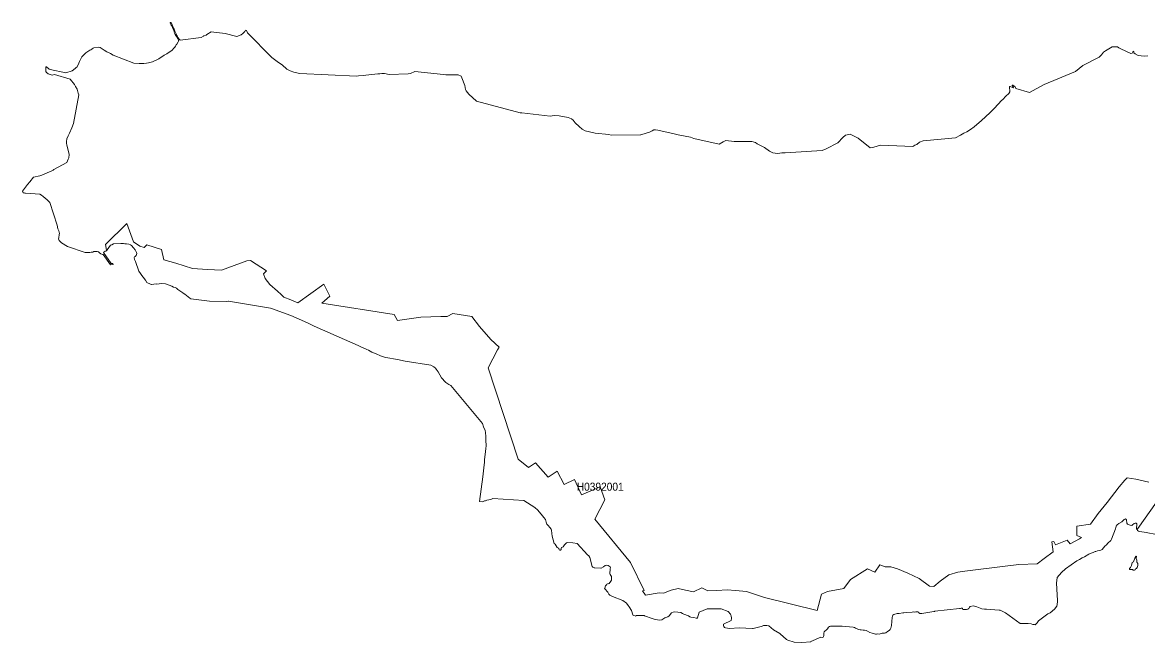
# Model space of a CAD drawing. Extents: x 369010 to 739155, y 6377141 to 6616555.
# Drawn here: x 387051 to 401092, y 6528037 to 6535786 of the extents above; entities that cross this region are included whole.
import ezdxf
from ezdxf.enums import TextEntityAlignment as Align

# ---------------------------------------------------------------- set-up
doc = ezdxf.new("R2010")
doc.units = 0
doc.header["$LTSCALE"] = 40
doc.layers.add('1', color=7, linetype='Continuous', lineweight=13)
doc.layers.add('2', color=7, linetype='Continuous')

msp = doc.modelspace()

# ---------------------------------------------------------------- linework, layer by layer
at = {"layer": '1'}
for points in [[(388996.8, 6535593.69), (388984.06, 6535610.9), (388982.57, 6535617.52), (388970.32, 6535638.04), (388969.82, 6535644.17), (388953.44, 6535678.26), (388945.83, 6535700.6), (388939.21, 6535715.99), (388913.22, 6535777.56), (388908.59, 6535784.35), (388900.97, 6535786.33), (388897.5, 6535781.7), (388898.99, 6535768.96), (388907.92, 6535752.41), (388911.9, 6535746.78), (388923.15, 6535724.44), (388942.52, 6535684.05), (388950.79, 6535654.59), (388959.4, 6535635.73), (388973.13, 6535610.73), (388990.51, 6535583.26), (388999.12, 6535565.88), (388999.12, 6535551.65), (388996.63, 6535542.38), (388977.27, 6535513.91), (388971.15, 6535506.8), (388961.88, 6535490.91), (388953.77, 6535478.66), (388942.52, 6535466.41), (388921.66, 6535441.42), (388853.31, 6535394.59), (388822.69, 6535375.72), (388753.01, 6535329.87), (388674.4, 6535295.12), (388625.08, 6535283.04), (388601.58, 6535276.91), (388567.98, 6535272.78), (388507.24, 6535272.28), (388441.53, 6535277.91), (388183.51, 6535379.36), (388149.42, 6535397.07), (388103.08, 6535418.58), (388069.48, 6535438.94), (388057.23, 6535447.55), (388022.48, 6535474.69), (387996, 6535479.66), (387940.88, 6535469.06), (387935.92, 6535464.93), (387923.18, 6535455.82), (387919.04, 6535453.67), (387915.4, 6535450.69), (387906.29, 6535445.56), (387891.07, 6535439.44), (387880.81, 6535433.31), (387841.58, 6535406.83), (387792.1, 6535355.36), (387761.48, 6535297.27), (387755.35, 6535276.91), (387739.63, 6535241.66), (387734.5, 6535232.56), (387722.75, 6535222.79), (387710.5, 6535211.54), (387670.78, 6535179.93), (387593, 6535158.91), (387394.72, 6535198.63), (387383.63, 6535204.75), (387373.87, 6535214.35), (387365.26, 6535219.98), (387351.03, 6535231.23), (387345.9, 6535231.73), (387343.25, 6535228.75), (387343.25, 6535214.85), (387340.77, 6535187.87), (387341.26, 6535178.77), (387344.41, 6535174.63), (387349.87, 6535162.38), (387368.24, 6535148.15), (387373.87, 6535143.52), (387420.87, 6535129.78), (387452.32, 6535135.9), (387644.8, 6535078.14), (387699.91, 6535012.27), (387715.14, 6534987.78), (387732.52, 6534953.19), (387745.76, 6534901.72), (387752.87, 6534883.34), (387686.67, 6534522.55), (387668.3, 6534471.57), (387637.68, 6534404.21), (387619.81, 6534369.62), (387603.09, 6534330.89), (387599.45, 6534300.77), (387599.95, 6534275.78), (387603.59, 6534256.42), (387616.83, 6534202.46), (387632.05, 6534158.11), (387634.54, 6534138.08), (387629.08, 6534096.37), (387622.95, 6534079.49), (387612.69, 6534057.64)], [(397391, 6534391.63), (397330.75, 6534376.9), (397298.81, 6534348.93), (397235.92, 6534280.74), (397091.44, 6534208.42), (397040.63, 6534184.42), (396576.72, 6534156.29), (396535.18, 6534156.29), (396485.69, 6534149.66), (396452.26, 6534152.31), (396424.29, 6534157.61), (396381.42, 6534179.12), (396321.18, 6534221.82), (396227.67, 6534268.66), (396206.32, 6534284.72), (396160.81, 6534296.8), (396128.7, 6534296.8), (395938.87, 6534298.12), (395837.25, 6534312.85), (395803.81, 6534295.31), (395751.68, 6534267.34), (395436.06, 6534336.85), (395397.17, 6534354.23), (395242.09, 6534381.04), (395209.99, 6534388.98), (395155.2, 6534402.39), (394986.72, 6534439.79), (394958.59, 6534445.09), (394935.91, 6534446.41), (394914.56, 6534433.17), (394881.13, 6534414.47), (394840.91, 6534403.71), (394776.86, 6534383.69), (394770.08, 6534382.36), (394402.33, 6534379.72), (394377, 6534385.01), (394204.55, 6534401.07), (394081.41, 6534430.53), (394044.01, 6534454.52), (394002.63, 6534487.96), (393953.15, 6534533.47), (393928.99, 6534566.9), (393907.64, 6534582.95), (393866.09, 6534597.52), (393756.53, 6534619.03), (393693.64, 6534623.01), (393644.15, 6534613.57), (393288.48, 6534655.11), (393268.46, 6534659.09), (392722.96, 6534804.9), (392627.96, 6534889.14), (392591.88, 6534930.51), (392583.77, 6534947.89), (392575.82, 6534997.38), (392541.07, 6535093.7), (392528.99, 6535115.05), (392494.23, 6535132.43), (392454.18, 6535132.43), (392337.83, 6535132.43), (392308.37, 6535135.08), (391950.22, 6535174.13), (391935.82, 6535165.53), (391914.97, 6535155.27), (391896.1, 6535149.64), (391868.13, 6535145.17), (391630.8, 6535136.23), (391572.21, 6535148.48), (391541.09, 6535148.98), (391514.61, 6535146.33), (391488.13, 6535142.36), (391339.18, 6535126.97), (391307.57, 6535123.99), (391249.97, 6535119.85), (391223.49, 6535114.22), (390514.97, 6535149.47), (390495.11, 6535150.96), (390442.15, 6535164.2), (390393.16, 6535181.58), (390354.43, 6535200.95), (390292.86, 6535255.89), (390247.35, 6535286.51), (390163.77, 6535350.23), (389861.39, 6535655.25), (389847.49, 6535684.38), (389837.4, 6535689.51), (389827.13, 6535674.12), (389817.04, 6535660.88), (389804.79, 6535649.63), (389783.28, 6535633.9), (389727.34, 6535613.05), (389582.52, 6535650.29), (389406.59, 6535670.65), (389355.12, 6535636.39), (389343.53, 6535629.27), (389317.88, 6535619.17), (389310.26, 6535614.04), (389283.78, 6535599.81), (389019.97, 6535564.39), (389009.05, 6535575.81), (388996.8, 6535593.69)], [(401108.71, 6535367.44), (401062.54, 6535364.8), (400989.05, 6535375.55), (400948.18, 6535392.93), (400934.27, 6535404.85), (400934.6, 6535411.96), (400934.6, 6535422.56), (400926.49, 6535426.69), (400918.55, 6535421.23), (400911.76, 6535403.85), (400895.71, 6535399.88), (400768.77, 6535455.99), (400744.61, 6535469.39), (400728.55, 6535481.48), (400661.69, 6535481.97), (400580.26, 6535430.67), (400556.1, 6535414.61), (400530.77, 6535383.83), (400501.31, 6535353.04), (400296.75, 6535247.45), (400203.08, 6535173.97), (399812.65, 6535009.46), (399806.03, 6535005.49), (399628.12, 6534911.81), (399459.63, 6534959.97), (399450.2, 6534983.97), (399438.28, 6534992.08), (399422.23, 6535001.35), (399412.79, 6535002.67), (399412.79, 6534994.73), (399424.88, 6534983.97), (399431.5, 6534970.73), (399428.85, 6534967.92), (399424.88, 6534967.92), (399390.12, 6534986.62), (399378.04, 6534986.62), (399378.04, 6534974.7), (399384.66, 6534931.84), (399384.66, 6534921.24), (399371.42, 6534899.73), (399335.34, 6534866.3), (399297.77, 6534823.6), (399281.72, 6534810.19), (399192.18, 6534713.87), (399134.75, 6534656.44), (399032.3, 6534559.45), (399031.64, 6534560.11), (398938.13, 6534482.66), (398891.29, 6534449.23), (398845.78, 6534421.09), (398808.37, 6534401.07), (398769.65, 6534376.9), (398705.43, 6534344.79), (398300.28, 6534306.07), (398257.41, 6534288.69), (398221.33, 6534262.04), (398198.66, 6534253.93), (398170.52, 6534237.88), (397770.83, 6534251.28), (397740.05, 6534245.99), (397674.51, 6534221.82), (397637.6, 6534221.49), (397489.97, 6534340.82), (397439.16, 6534364.99), (397391, 6534391.63)], [(387612.69, 6534057.64), (387603.09, 6534037.78), (387441.39, 6533948.08), (387432.29, 6533941.96), (387416.9, 6533930.21), (387291.61, 6533878.24), (387269.6, 6533870.13), (387189.66, 6533852.25), (387141.17, 6533794.66), (387114.19, 6533761.56), (387050.97, 6533677.81), (387056.6, 6533666.72), (387059.08, 6533656.46), (387072.15, 6533656.3), (387081.26, 6533654.15), (387090.03, 6533654.15), (387266.13, 6533638.59), (387286.48, 6533629.49), (387309.49, 6533611.61), (387357.32, 6533571.39), (387390.92, 6533536.14), (387482.77, 6533252.3), (387493.86, 6533208.94), (387496.01, 6533200.83), (387505.11, 6533182.46), (387511.73, 6533147.87), (387510.24, 6533134.46), (387507.1, 6533096.89), (387502.13, 6533081.01), (387510.74, 6533061.64), (387520.5, 6533050.39), (387540.37, 6533030.53), (387612.19, 6532986.17), (387834.13, 6532910.04), (387846.38, 6532910.04), (387854, 6532912.52), (387893.88, 6532911.53), (387910.6, 6532914.67), (387928.97, 6532915.67), (387944.19, 6532923.78), (387955.45, 6532925.27), (387961.08, 6532925.27), (387984.08, 6532923.28), (388001.29, 6532918.15), (388012.05, 6532908.55), (388029.43, 6532894.65), (388049.29, 6532888.03), (388060.54, 6532886.54), (388152.23, 6532756.62), (388184.84, 6532761.25), (388180.2, 6532774.99), (388158.36, 6532772.34), (388063.52, 6532911.03), (388084.38, 6532927.42), (388094.64, 6532932.88), (388101.75, 6532933.54), (388103.24, 6532934.53)], [(390063.47, 6532644.08), (390100.38, 6532682.31), (389897.64, 6532813.39), (389853.95, 6532805.44), (389536.18, 6532690.25), (389361.41, 6532698.19), (389174.72, 6532710.11), (388968, 6532777.64), (388817.06, 6532821.33), (388789.26, 6532948.44), (388602.57, 6533008.02), (388570.79, 6532972.27), (388515.18, 6532992.13), (388435.74, 6533043.77), (388356.3, 6533274.15), (388086.03, 6533011.99), (388101.92, 6532940.49), (388103.24, 6532934.53)], [(388103.24, 6532934.53), (388101.92, 6532940.49), (388086.03, 6533011.99), (388356.3, 6533274.15), (388435.74, 6533043.77), (388515.18, 6532992.13), (388570.79, 6532972.27), (388602.57, 6533008.02), (388789.26, 6532948.44), (388817.06, 6532821.33), (388968, 6532777.64), (389174.72, 6532710.11), (389361.41, 6532698.19), (389536.18, 6532690.25), (389853.95, 6532805.44), (389897.64, 6532813.39), (390100.38, 6532682.31), (390063.47, 6532644.08), (390083.33, 6532588.47), (390138.94, 6532513), (390238.25, 6532429.42), (390281.94, 6532385.72), (390313.72, 6532353.95), (390401.1, 6532318.2), (390488.49, 6532282.45), (390814.37, 6532516.97), (390889.84, 6532365.86), (390790.53, 6532278.48), (391694.68, 6532135.65), (391734.4, 6532060.01), (392028.34, 6532103.7), (392278.25, 6532111.81), (392357.69, 6532111.81), (392425.22, 6532147.56), (392663.54, 6532111.81), (392759.04, 6531988.51), (392902.03, 6531825.49), (393005.31, 6531730.16), (392985.45, 6531694.41), (392865.95, 6531469.16), (393242.64, 6530330.33), (393369.75, 6530223.08), (393457.13, 6530282.66), (393616.02, 6530103.75), (393731.21, 6530179.39), (393818.76, 6530012.4), (393945.87, 6530075.95), (394033.25, 6529881.15), (394267.61, 6529984.59), (394323.22, 6529821.57), (394198.76, 6529577.78), (394647.77, 6529037.08), (394814.6, 6528687.37), (394794.74, 6528683.4), (394834.46, 6528627.79), (395005.26, 6528659.57), (395056.89, 6528655.59), (395152.23, 6528691.34), (395239.61, 6528711.2), (395330.97, 6528691.34), (395434.24, 6528671.48), (395537.68, 6528719.15), (395610.84, 6528683.56), (395726.03, 6528687.54), (395853.13, 6528695.48), (395956.41, 6528687.54), (396095.43, 6528675.62), (396318.04, 6528599.98), (396977.4, 6528437.13), (397033.01, 6528643.68), (397104.68, 6528675.62), (397311.22, 6528711.37), (397394.64, 6528826.56), (397605.16, 6528957.8), (397696.52, 6528918.08), (397759.24, 6529008.95), (397826.77, 6528985.11), (397898.27, 6528985.11), (397981.68, 6528957.31), (398108.79, 6528905.51), (398251.95, 6528837.98), (398379.06, 6528742.65), (398434.67, 6528738.68), (398513.28, 6528806.2), (398620.53, 6528881.67), (398735.72, 6528917.42), (398823.1, 6528929.34), (399326.07, 6528992.73), (399496.87, 6529012.59), (399727.42, 6529020.53), (399814.8, 6529088.22), (399926.02, 6529171.64), (399910.13, 6529294.94), (399933.97, 6529298.91), (399953.83, 6529259.02), (400100.79, 6529314.8), (400136.54, 6529271.1), (400255.71, 6529334.66), (400279.54, 6529350.55), (400219.96, 6529374.38)], [(388103.24, 6532934.53), (388106.39, 6532936.52), (388107.88, 6532943.14), (388150.74, 6533001.73), (388166.96, 6533006.36), (388189.97, 6533019.11), (388280.66, 6533025.23), (388310.79, 6533024.24), (388329.16, 6533020.1), (388352, 6533019.11), (388378.97, 6533015.96), (388400.49, 6533007.85), (388411.58, 6532997.76), (388437.23, 6532971.61), (388457.09, 6532945.62), (388472.32, 6532918.65), (388474.8, 6532910.54), (388477.45, 6532898.79), (388475.96, 6532884.55), (388472.32, 6532874.79), (388464.71, 6532866.68), (388458.58, 6532862.04), (388451.46, 6532858.07), (388447.82, 6532849.8), (388448.82, 6532824.31), (388453.95, 6532813.72), (388464.21, 6532798.32), (388504.43, 6532678.17), (388552.92, 6532609.32), (388557.88, 6532602.7), (388588.5, 6532565.96), (388605.88, 6532538.48), (388649.24, 6532513.99), (388656.36, 6532513), (388662.48, 6532512.5), (388722.56, 6532518.62), (388729.68, 6532516.97), (388788.27, 6532522.6), (388838.74, 6532521.11), (388917.36, 6532489.49), (388939.21, 6532479.9), (388958.57, 6532472.61), (388972.8, 6532465), (388990.18, 6532451.26), (389005.9, 6532439.02), (389051.91, 6532407.9), (389070.12, 6532395.65), (389080.88, 6532390.19), (389120.6, 6532356.93), (389140.46, 6532339.71), (389155.85, 6532332.43), (389386.73, 6532304.46), (389605.36, 6532300.99), (389619.1, 6532303.96), (389624.23, 6532303.96), (390149.7, 6532217.9), (390162.45, 6532213.27), (390402.59, 6532125.55), (390611.46, 6532034.36), (390620.23, 6532029.72), (390696.2, 6531991.49), (391245.67, 6531751.02), (391260.4, 6531740.26), (391269.5, 6531738.27), (391352.09, 6531699.38), (391371.45, 6531690.77), (391413.82, 6531666.28), (391447.91, 6531654.03), (391543.74, 6531613.32), (391588.59, 6531601.07), (391735.56, 6531574.92), (391832.71, 6531551.58), (392152.63, 6531502.43), (392189.87, 6531481.08), (392208.24, 6531466.85), (392219.99, 6531454.1), (392243.33, 6531421.99), (392263.19, 6531382.11), (392286.69, 6531344.37), (392300.92, 6531326.66), (392317.8, 6531306.14), (392339.15, 6531287.94), (392375.4, 6531261.95), (392402.38, 6531248.55), (392797.43, 6530774.05), (392811.67, 6530734.82), (392829.05, 6530688.98), (392834.18, 6530662.99), (392837.16, 6530610.03), (392839.14, 6530569.15), (392841.29, 6530493.19), (392840.8, 6530466.21), (392834.18, 6530422.35), (392820.77, 6530326.52), (392820.27, 6530288.29), (392816.3, 6530258.17), (392801.74, 6530109.22), (392761.19, 6529798.07), (392795.28, 6529797.41), (392823.91, 6529807.67)], [(401120.46, 6530040.53), (400957.11, 6530078.76), (400851.02, 6530093.66), (400819.25, 6530064.36), (400751.39, 6529983.76), (400598.47, 6529786.15), (400486.09, 6529650.27), (400390.76, 6529517.54), (400219.96, 6529493.54), (400219.96, 6529374.38), (400279.54, 6529350.55), (400255.71, 6529334.66), (400136.54, 6529271.1), (400100.79, 6529314.8), (399953.83, 6529259.02), (399933.97, 6529298.91), (399910.13, 6529294.94), (399926.02, 6529171.64), (399814.8, 6529088.22), (399727.42, 6529020.53), (399496.87, 6529012.59), (399326.07, 6528992.73), (398823.1, 6528929.34), (398735.72, 6528917.42), (398620.53, 6528881.67), (398513.28, 6528806.2), (398434.67, 6528738.68), (398379.06, 6528742.65), (398251.95, 6528837.98), (398108.79, 6528905.51), (397981.68, 6528957.31), (397898.27, 6528985.11), (397826.77, 6528985.11), (397759.24, 6529008.95), (397696.52, 6528918.08), (397605.16, 6528957.8), (397394.64, 6528826.56), (397311.22, 6528711.37), (397104.68, 6528675.62), (397033.01, 6528643.68), (396977.4, 6528437.13), (396318.04, 6528599.98), (396095.43, 6528675.62), (395956.41, 6528687.54), (395853.13, 6528695.48), (395726.03, 6528687.54), (395610.84, 6528683.56), (395537.68, 6528719.15), (395434.24, 6528671.48), (395330.97, 6528691.34), (395239.61, 6528711.2), (395152.23, 6528691.34), (395056.89, 6528655.59), (395005.26, 6528659.57), (394834.46, 6528627.79), (394794.74, 6528683.4), (394814.6, 6528687.37), (394647.77, 6529037.08), (394198.76, 6529577.78), (394323.22, 6529821.57), (394267.61, 6529984.59), (394033.25, 6529881.15), (393945.87, 6530075.95), (393818.76, 6530012.4), (393731.21, 6530179.39), (393616.02, 6530103.75), (393457.13, 6530282.66), (393369.75, 6530223.08), (393242.64, 6530330.33), (392865.95, 6531469.16), (392985.45, 6531694.41), (393005.31, 6531730.16), (392902.03, 6531825.49), (392759.04, 6531988.51), (392663.54, 6532111.81), (392425.22, 6532147.56), (392357.69, 6532111.81), (392278.25, 6532111.81), (392028.34, 6532103.7), (391734.4, 6532060.01), (391694.68, 6532135.65), (390790.53, 6532278.48), (390889.84, 6532365.86), (390814.37, 6532516.97), (390488.49, 6532282.45), (390401.1, 6532318.2), (390313.72, 6532353.95), (390281.94, 6532385.72), (390238.25, 6532429.42), (390138.94, 6532513), (390083.33, 6532588.47), (390063.47, 6532644.08)], [(400219.96, 6529374.38), (400219.96, 6529493.54), (400390.76, 6529517.54), (400486.09, 6529650.27), (400598.47, 6529786.15), (400751.39, 6529983.76), (400819.25, 6530064.36), (400851.02, 6530093.66), (400957.11, 6530078.76), (401120.46, 6530040.53)], [(392823.91, 6529807.67), (392833.02, 6529810.15), (392849.4, 6529815.78), (392874.89, 6529821.4), (392895.25, 6529823.39), (392908.49, 6529829.51), (392919.25, 6529831.67), (392925.37, 6529835.64), (393314.3, 6529811.31), (393450.35, 6529725.58), (393487.75, 6529689.66), (393504.14, 6529670.3), (393528.63, 6529640.67), (393562.72, 6529600.46), (393583.08, 6529575.96), (393587.72, 6529558.25), (393591.69, 6529540.38), (393602.45, 6529517.87), (393616.68, 6529498.01), (393638.19, 6529475.67), (393655.57, 6529455.14), (393659.05, 6529443.56), (393661.53, 6529401.69), (393665.67, 6529367.1), (393693.14, 6529276.73), (393702.91, 6529265.64), (393717.64, 6529244.13), (393731.37, 6529225.92), (393745.28, 6529216.16), (393751.9, 6529211.03), (393754.38, 6529197.79), (393762.49, 6529191.17), (393771.76, 6529191.17), (393777.88, 6529200.93), (393779.37, 6529214.17), (393785.99, 6529223.77), (393794.6, 6529230.39), (393805.85, 6529235.02), (393813.46, 6529246.28), (393822.73, 6529259.52), (393833.32, 6529270.77), (393845.57, 6529281.36), (393855.34, 6529286), (393924.68, 6529285.01), (393978.64, 6529276.73), (394108.56, 6529134.56), (394112.2, 6529129.93), (394121.8, 6529126.45), (394126.93, 6529118.84), (394137.19, 6529101.96), (394168.3, 6528986.77), (394177.41, 6528977.67), (394193.79, 6528971.04), (394200.41, 6528971.04), (394274.72, 6528968.4), (394280.85, 6528965.91), (394309.48, 6528985.28), (394327.35, 6529001.5), (394348.7, 6529002.66), (394366.08, 6528998.02), (394391.57, 6528981.64), (394396.53, 6528969.89), (394393.55, 6528962.27), (394391.07, 6528949.03), (394388.42, 6528903.68), (394388.42, 6528896.57), (394393.06, 6528885.81), (394408.28, 6528860.82), (394407.79, 6528814.97), (394402.16, 6528802.23), (394380.81, 6528775.25), (394367.07, 6528769.13), (394357.31, 6528769.13), (394348.21, 6528766.65), (394344.57, 6528758.37), (394341.09, 6528752.25), (394331.82, 6528744.64), (394328.84, 6528739.01), (394328.84, 6528724.28), (394324.71, 6528716.67), (394321.73, 6528710.54), (394325.7, 6528706.9), (394362.44, 6528667.18), (394375.18, 6528641.2), (394388.92, 6528629.44), (394421.03, 6528613.72), (394550.95, 6528561.75), (394594.81, 6528530.64), (394615.33, 6528501.51), (394629.07, 6528481.65), (394659.52, 6528437.29), (394673.92, 6528383.34), (394681.04, 6528375.56), (394703.38, 6528368.94), (394712.15, 6528368.44), (394715.13, 6528374.57), (394814.6, 6528374.07), (394821.71, 6528372.58), (394916.55, 6528335.84), (394942.53, 6528329.72)], [(400969.86, 6529522.67), (400968.37, 6529458.12), (400973.33, 6529447.86), (400982.6, 6529460.94), (401215.96, 6529792.11)], [(401215.96, 6529792.11), (400982.6, 6529460.94), (400973.33, 6529447.86), (400978.63, 6529437.27), (400992.53, 6529429.16), (401009.08, 6529426.02), (401088.85, 6529410.62), (401214.97, 6529386.29)], [(397934.18, 6528385.66), (397977.54, 6528400.88), (398003.53, 6528400.88), (398046.39, 6528408), (398061.12, 6528409.49), (398095.22, 6528410.98), (398163.07, 6528417.1), (398175.82, 6528419.25), (398192.53, 6528417.77), (398209.41, 6528420.25), (398224.64, 6528421.74), (398235.4, 6528419.25), (398245.66, 6528414.62), (398249.14, 6528410.48), (398258.9, 6528400.39), (398270.65, 6528398.9), (398282.9, 6528401.88), (398434.17, 6528424.39), (398443.93, 6528425.38), (398449.06, 6528429.85), (398756.24, 6528461.46), (398761.87, 6528463.94), (398769.48, 6528464.6), (398777.09, 6528467.09), (398788.84, 6528466.09), (398793.48, 6528461.95), (398794.47, 6528453.84), (398799.6, 6528450.2), (398843.96, 6528451.86), (398860.67, 6528453.35), (398871.93, 6528462.45), (398882.19, 6528480.33), (398889.8, 6528486.45), (398924.89, 6528494.06), (398972.88, 6528483.3), (399033.46, 6528456.66), (399068.88, 6528453.51), (399092.38, 6528452.36), (399252.42, 6528442.76), (399264.5, 6528439.78), (399328.39, 6528407.67), (399515.08, 6528276.09), (399605.28, 6528274.6), (399614.54, 6528276.42), (399651.78, 6528272.62), (399672.97, 6528262.69), (399684.06, 6528261.03), (399692, 6528262.19), (399700.61, 6528259.54), (399724.77, 6528284.2), (399740.49, 6528308.37), (399860.15, 6528397.41), (399889.94, 6528408.83), (399942.08, 6528452.52), (399971.87, 6528492.41), (399977.49, 6528512.93), (399981.63, 6528551), (399981.3, 6528591.71), (399977.49, 6528603.3), (399975.51, 6528632.59), (399966.57, 6528781.21), (399976.34, 6528850.06), (400029.63, 6528911.3), (400078.45, 6528956.81), (400222.27, 6529058.43), (400256.37, 6529075.64), (400286.82, 6529094.18), (400318.27, 6529108.74), (400368.91, 6529141.18), (400399.36, 6529155.42), (400426.34, 6529164.19), (400449.01, 6529174.28), (400460.1, 6529176.1), (400481.12, 6529183.88), (400522, 6529191.99), (400536.24, 6529201.26), (400572.81, 6529239.99), (400590.19, 6529257.37), (400608.73, 6529277.06), (400643.81, 6529312.81), (400653.08, 6529330.19), (400702.9, 6529458.79), (400713.99, 6529492.55), (400726.57, 6529508.77), (400747.25, 6529526.81), (400782.67, 6529546.17), (400805.84, 6529565.7), (400814.28, 6529576.13), (400827.69, 6529582.25), (400838.28, 6529576.13), (400843.41, 6529569.18), (400845.73, 6529529.62), (400855.33, 6529517.7), (400887.27, 6529502.97), (400906.14, 6529501.15), (400917.56, 6529506.45), (400937.25, 6529526.48), (400949.33, 6529529.62), (400960.59, 6529529.12), (400969.86, 6529522.67)], [(394942.53, 6528329.72), (395002.61, 6528314.99), (395036.21, 6528322.6), (395072.95, 6528345.11), (395112.17, 6528358.85), (395127.56, 6528369.44), (395156.03, 6528407.01), (395176.89, 6528414.95), (395197.9, 6528422.07), (395274.37, 6528411.81), (395294.72, 6528398.57), (395311.44, 6528392.44), (395368.54, 6528369.44), (395386.91, 6528358.85), (395397.67, 6528356.2), (395437.39, 6528348.58), (395464.86, 6528342.46), (395477.61, 6528340.97), (395483.73, 6528346.6), (395504.25, 6528415.61), (395601.57, 6528456.66), (395777.33, 6528459.31), (395866.04, 6528425.05), (395894.18, 6528390.46), (395897.16, 6528384.33), (395901.79, 6528364.97), (395907.42, 6528345.11), (395906.76, 6528339.48), (395901.79, 6528312.01), (395807.46, 6528265), (395807.46, 6528250.27), (395811.1, 6528238.52), (395820.7, 6528224.79), (395831.95, 6528220.65), (395880.77, 6528212.04), (396001.59, 6528220.15), (396169.91, 6528212.54), (396178.52, 6528214.03), (396277.32, 6528238.52), (396288.58, 6528243.65), (396307.44, 6528248.29), (396325.81, 6528250.27), (396347.66, 6528250.27), (396373.15, 6528246.63), (396431.9, 6528194.67), (396509.36, 6528149.81), (396515.48, 6528144.19), (396596.41, 6528076), (396609.65, 6528066.23), (396690.58, 6528043.89), (396784.59, 6528037.27), (396898.29, 6528046.87), (396898.29, 6528050.51), (397023.08, 6528104.47), (397039.96, 6528101.98), (397051.05, 6528103.47), (397057.18, 6528112.58), (397059.33, 6528123.83), (397058.83, 6528154.94), (397065.95, 6528169.18), (397075.05, 6528180.43), (397092.92, 6528194.17), (397107.65, 6528209.56), (397118.91, 6528227.27), (397131.65, 6528239.02), (397145.39, 6528242.66), (397158.63, 6528243.65), (397277.46, 6528242.17), (397290.7, 6528243.16), (397425.75, 6528228.76), (397444.62, 6528223.79), (397458.36, 6528217.17), (397467.13, 6528212.04), (397495.6, 6528200.79), (397515.46, 6528197.31), (397528.2, 6528194.67), (397553.69, 6528191.69), (397569.58, 6528190.03), (397589.44, 6528187.55), (397606.15, 6528179.94), (397635.78, 6528164.54), (397664.24, 6528152.46), (397680.13, 6528148.32), (397706.12, 6528143.69), (397719.36, 6528143.19), (397737.23, 6528144.19), (397753.45, 6528142.7), (397764.21, 6528145.18), (397787.71, 6528152.46), (397820.31, 6528154.94), (397833.56, 6528160.08), (397854.91, 6528173.32), (397877.41, 6528185.56), (397888.5, 6528199.8), (397896.45, 6528218.33), (397904.06, 6528249.45), (397913.82, 6528350.4), (397917.3, 6528365.63), (397922.93, 6528377.38), (397934.18, 6528385.66)]]:
    msp.add_lwpolyline(points, dxfattribs=at)
msp.add_lwpolyline([(400963.9, 6529114.7), (400959.26, 6529113.38), (400946.19, 6529093.02), (400930.47, 6529046.51), (400913.92, 6529035.76), (400903.49, 6528998.02), (400891.57, 6528975.18), (400879.99, 6528963.27), (400878.83, 6528955.65), (400884.12, 6528949.03), (400894.55, 6528947.87), (400914.58, 6528951.85), (400926.16, 6528943.24), (400939.57, 6528941.75), (400949.66, 6528947.21), (400954.96, 6528957.14), (400966.55, 6528960.62), (400975.48, 6528974.02), (400982.43, 6529001), (400984.25, 6529024.5), (400968.86, 6529041.05), (400969.19, 6529066.04), (400963.57, 6529085.41), (400967.37, 6529111.23)], close=True, dxfattribs=at)

# ---------------------------------------------------------------- texts
at = {"layer": '2', "width": 0.95}
msp.add_text('H0392001', height=100, dxfattribs=at).set_placement((394267.6, 6529934.59), align=Align.CENTER)

doc.saveas('drawing.dxf')
